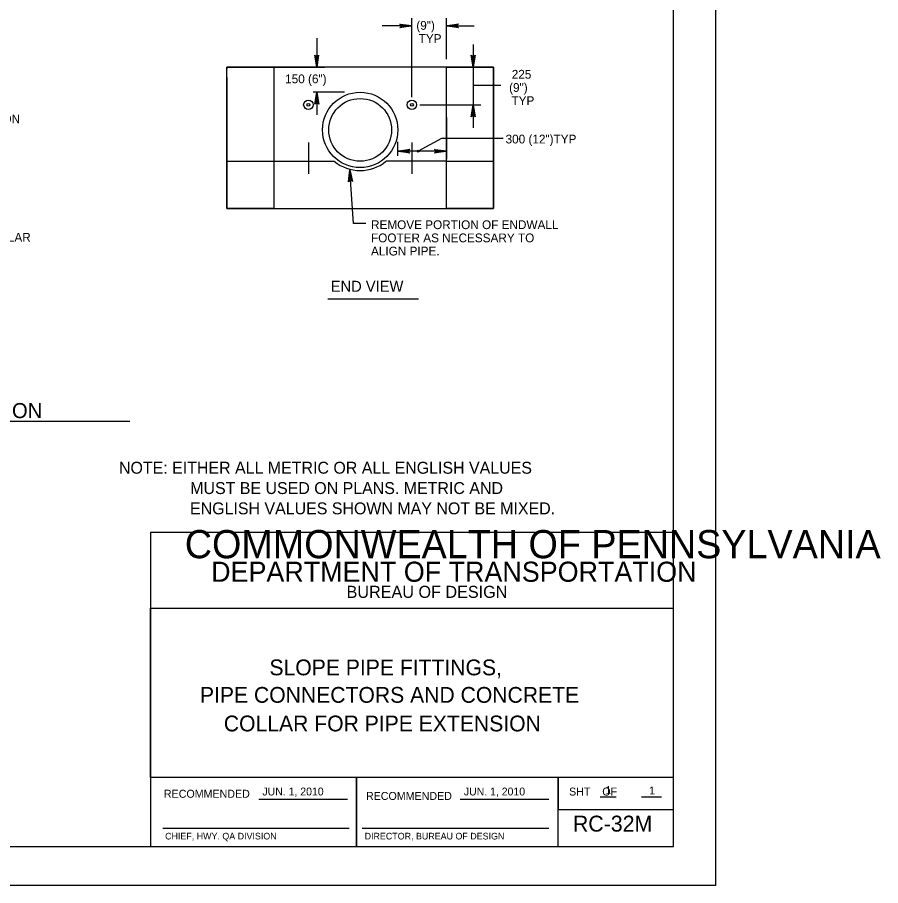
# Model space of a CAD drawing. Extents: x 637898 to 638802, y 298167 to 298761.
# Drawn here: x 638472.1 to 638802.1, y 298166.9 to 298498.8 of the extents above; entities that cross this region are included whole.
import ezdxf

# ---------------------------------------------------------------- set-up
doc = ezdxf.new("R2010")
doc.units = 0
for name, color, linetype in [('1', 7, 'Continuous'), ('2', 7, 'Continuous'), ('3', 7, 'Continuous'), ('40', 7, 'Continuous'), ('PLT-BNDY', 7, 'Continuous')]:
    doc.layers.add(name, color=color, linetype=linetype)

msp = doc.modelspace()

# ---------------------------------------------------------------- linework, layer by layer
at = {"layer": '1'}
for p, q in [((638694.84, 298200.85), (638700.98, 298200.85)), ((638710.65, 298200.85), (638718.3, 298200.85)), ((638564.44, 298199.87), (638598.33, 298199.87)), ((638641.44, 298199.87), (638675.31, 298199.87)), ((638527.74, 298188.79), (638598.98, 298188.79)), ((638603.91, 298188.79), (638675.24, 298188.79))]:
    msp.add_line(p, q, dxfattribs=at)
msp.add_lwpolyline([(638722.97, 298181.88), (638722.97, 298745.88), (637936.97, 298745.88), (637936.97, 298181.88), (638722.97, 298181.88), (638722.97, 298208.24), (638522.97, 298208.24), (638522.97, 298272.92), (638722.97, 298272.92), (638722.97, 298301.88), (638522.97, 298301.88), (638522.97, 298181.88), (638601.78, 298181.88), (638601.78, 298208.24), (638601.78, 298181.88), (638678.78, 298181.88), (638678.78, 298208.24), (638678.78, 298195.92), (638722.97, 298195.92)], dxfattribs=at)
at = {"layer": '2'}
for p, q in [((638622.95, 298468.33), (638622.95, 298498.53)), ((638636.15, 298482.76), (638636.15, 298498.53)), ((638622.95, 298495.53), (638611.58, 298495.53)), ((638636.15, 298495.53), (638646.71, 298495.53)), ((638586.58, 298490.78), (638586.58, 298479.76)), ((638646.34, 298488.43), (638646.34, 298479.76)), ((638552.15, 298479.76), (638589.58, 298479.76)), ((638639.15, 298479.76), (638649.34, 298479.76)), ((638597.15, 298470.16), (638585.24, 298470.16)), ((638646.36, 298472.82), (638656.92, 298472.82)), ((638625.95, 298465.36), (638649.34, 298465.36)), ((638636.15, 298460.48), (638636.15, 298444.62)), ((638583.35, 298450.96), (638583.35, 298438.96)), ((638617.55, 298445.82), (638617.55, 298451.21)), ((638622.95, 298450.96), (638622.95, 298438.96)), ((638636.15, 298447.62), (638617.55, 298447.62)), ((638570.15, 298443.76), (638593.27, 298443.76)), ((638583.35, 298443.76), (638583.35, 298443.76)), ((638636.15, 298443.76), (638613.03, 298443.76)), ((638622.95, 298443.76), (638622.95, 298443.76))]:
    msp.add_line(p, q, dxfattribs=at)
for points in [[(638618.59, 298496.05), (638618.75, 298495.73), (638622.95, 298495.53), (638618.59, 298496.05), (638618.36, 298496.24), (638622.95, 298495.53), (638618.76, 298495.3), (638618.61, 298494.98), (638622.95, 298495.53), (638618.37, 298494.77), (638618.61, 298494.98)], [(638640.51, 298495.01), (638640.35, 298495.33), (638636.15, 298495.53), (638640.51, 298495.01), (638640.74, 298494.82), (638636.15, 298495.53), (638640.34, 298495.76), (638640.49, 298496.08), (638636.15, 298495.53), (638640.73, 298496.29), (638640.49, 298496.08)], [(638587.1, 298484.12), (638586.78, 298483.96), (638586.58, 298479.76), (638587.1, 298484.12), (638587.29, 298484.35), (638586.58, 298479.76), (638586.34, 298483.95), (638586.03, 298484.1), (638586.58, 298479.76), (638585.82, 298484.34), (638586.03, 298484.1)], [(638646.86, 298484.12), (638646.54, 298483.96), (638646.34, 298479.76), (638646.86, 298484.12), (638647.05, 298484.35), (638646.34, 298479.76), (638646.1, 298483.95), (638645.79, 298484.1), (638646.34, 298479.76), (638645.58, 298484.34), (638645.79, 298484.1)], [(638552.15, 298475.75), (638552.15, 298425.76), (638654.15, 298425.76), (638654.15, 298479.76), (638552.15, 298479.76), (638552.15, 298478.99)], [(638646.34, 298479.76), (638646.34, 298465.36)], [(638586.06, 298465.8), (638586.37, 298465.96), (638586.58, 298470.16), (638586.06, 298465.8), (638585.87, 298465.57), (638586.58, 298470.16), (638586.81, 298465.97), (638587.13, 298465.82), (638586.58, 298470.16), (638587.33, 298465.58), (638587.13, 298465.82)], [(638586.58, 298470.16), (638586.58, 298461.52)], [(638645.82, 298461), (638646.13, 298461.16), (638646.34, 298465.36), (638645.82, 298461), (638645.63, 298460.77), (638646.34, 298465.36), (638646.57, 298461.17), (638646.89, 298461.02), (638646.34, 298465.36), (638647.09, 298460.78), (638646.89, 298461.02)], [(638646.34, 298465.36), (638646.34, 298456.53)], [(638657.84, 298452.48), (638643.78, 298452.48), (638634.18, 298452.48), (638625.34, 298447.62)], [(638621.91, 298447.1), (638621.75, 298447.41), (638617.55, 298447.62), (638621.91, 298447.1), (638622.14, 298446.91), (638617.55, 298447.62), (638621.74, 298447.85), (638621.89, 298448.17), (638617.55, 298447.62), (638622.13, 298448.38), (638621.89, 298448.17)], [(638631.79, 298448.14), (638631.95, 298447.82), (638636.15, 298447.62), (638631.79, 298448.14), (638631.56, 298448.33), (638636.15, 298447.62), (638631.96, 298447.38), (638631.81, 298447.07), (638636.15, 298447.62), (638631.57, 298446.86), (638631.81, 298447.07)], [(638598.93, 298436.16), (638599.23, 298436.34), (638599.18, 298440.54), (638598.93, 298436.16), (638598.75, 298435.92), (638599.18, 298440.54), (638599.67, 298436.37), (638599.99, 298436.24), (638599.18, 298440.54), (638600.21, 298436.02), (638599.99, 298436.24)], [(638605.36, 298419.94), (638600.56, 298419.94), (638599.18, 298440.54)]]:
    msp.add_lwpolyline(points, dxfattribs=at)
for points in [[(638552.15, 298425.76), (638552.15, 298479.76), (638570.15, 298479.76), (638570.15, 298425.76)], [(638636.15, 298425.76), (638636.15, 298479.76), (638654.15, 298479.76), (638654.15, 298425.76)], [(638552.15, 298425.76), (638552.15, 298443.76), (638570.15, 298443.76), (638570.15, 298425.76)], [(638636.15, 298425.76), (638636.15, 298443.76), (638654.15, 298443.76), (638654.15, 298425.76)]]:
    msp.add_lwpolyline(points, close=True, dxfattribs=at)
for centre, radius in [((638603.15, 298455.76), 14.4), ((638583.35, 298465.36), 1.8), ((638603.15, 298455.76), 12), ((638622.95, 298465.36), 1.8), ((638583.35, 298465.36), 0.536), ((638622.95, 298465.36), 0.536), ((638625.34, 298447.62), 0.343)]:
    msp.add_circle(centre, radius, dxfattribs=at)
msp.add_arc((638603.15, 298455.76), 15.54, 230.5354, 309.4646, dxfattribs=at)
at = {"layer": '3'}
for p, q in [((638590.76, 298391.18), (638625.43, 298391.18)), ((638319.38, 298344.38), (638515.14, 298344.38))]:
    msp.add_line(p, q, dxfattribs=at)
at = {"layer": 'PLT-BNDY'}
msp.add_lwpolyline([(637897.97, 298760.88), (638738.97, 298760.88), (638738.97, 298166.88), (637897.97, 298166.88)], close=True, dxfattribs=at)

# ---------------------------------------------------------------- texts
at = {"layer": '1'}
for s, height, p in [('COMMONWEALTH OF PENNSYLVANIA', 10.7834, (638536.12, 298292.02)), ('DEPARTMENT OF TRANSPORTATION', 7.6843, (638546.19, 298283.03)), ('BUREAU OF DESIGN', 4.6221, (638597.96, 298276.87)), ('SLOPE PIPE FITTINGS,', 6.04, (638568.48, 298247.28)), ('PIPE CONNECTORS AND CONCRETE', 6.04, (638541.91, 298236.78)), ('COLLAR FOR PIPE EXTENSION', 6.04, (638551.04, 298225.84)), ('JUN. 1, 2010', 3, (638565.78, 298201.36)), ('JUN. 1, 2010', 3, (638642.78, 298201.36)), ('SHT    OF', 3.048, (638683.02, 298201.31)), ('1', 3.05, (638696.89, 298201.86)), ('1', 3.05, (638713.6, 298201.72)), ('RECOMMENDED', 3.048, (638528.14, 298200.47)), ('RECOMMENDED', 3.048, (638605.38, 298199.64)), ('APPROVED', 0.0192, (638566, 298199.81)), ('RC-32M', 6.096, (638684.47, 298187.53)), ('CHIEF, HWY. QA DIVISION', 2.54, (638528.59, 298184.53)), ('DIRECTOR, BUREAU OF DESIGN', 2.54, (638604.86, 298184.53))]:
    msp.add_text(s, height=height, dxfattribs=at).set_placement(p)
at = {"layer": '3'}
for s, height, p in [('(9")', 3.36, (638624.62, 298494.04)), ('TYP', 3.36, (638625.52, 298489)), ('150 (6")', 3.36, (638574.48, 298473.59)), ('225', 3.36, (638661.09, 298475.34)), ('(9")', 3.36, (638660.09, 298470.3)), ('TYP', 3.36, (638660.99, 298465.26)), ('PIPE EXTENSION', 3.36, (638435.71, 298458.26)), ('300 (12")TYP', 3.36, (638658.74, 298450.58)), ('REMOVE PORTION OF ENDWALL', 3.36, (638607.3, 298417.84)), ('CONCRETE COLLAR', 3.36, (638432.8, 298413)), ('FOOTER AS NECESSARY TO', 3.36, (638607.3, 298412.8)), ('ALIGN PIPE.', 3.36, (638607.3, 298407.76)), ('END VIEW', 4.2, (638591.89, 298393.88)), ('CONCRETE COLLAR FOR PIPE EXTENSION', 5.76, (638320.71, 298345.59))]:
    msp.add_text(s, height=height, dxfattribs=at).set_placement(p)
at = {"layer": '40'}
for s, p in [('NOTE: EITHER ALL METRIC OR ALL ENGLISH VALUES', (638510.96, 298324.34)), ('MUST BE USED ON PLANS. METRIC AND', (638538.19, 298316.57)), ('ENGLISH VALUES SHOWN MAY NOT BE MIXED.', (638538.12, 298308.81))]:
    msp.add_text(s, height=4.5587, dxfattribs=at).set_placement(p)

doc.saveas('drawing.dxf')
